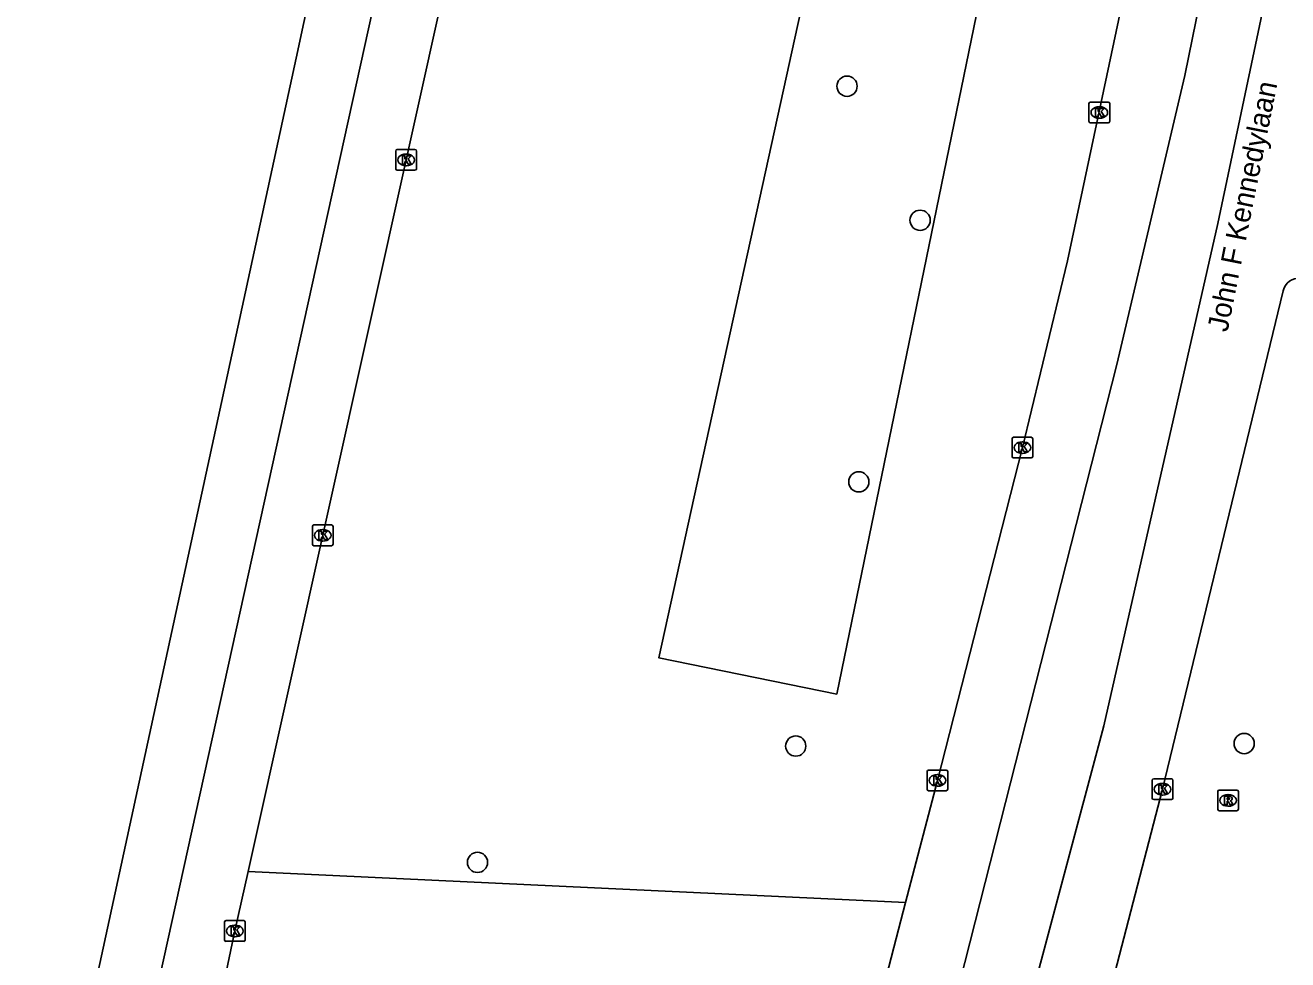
# Model space of a CAD drawing. Extents: x 161761 to 162722, y 384793 to 385405.
# Drawn here: x 161766 to 161827, y 384916.7 to 384961.8 of the extents above; entities that cross this region are included whole.
import ezdxf

# ---------------------------------------------------------------- set-up
doc = ezdxf.new("R2010")
doc.units = 0
for name, color, linetype in [('IMGEO_Berm_groen', 7, 'Continuous'), ('IMGEO_Boom', 7, 'Continuous'), ('IMGEO_Kolk', 7, 'Continuous'), ('IMGEO_Openbare_ruimte_label', 7, 'Continuous'), ('IMGEO_Rijbaan_regionaal_gesloten', 7, 'Continuous'), ('IMGEO_Rioolput', 7, 'Continuous')]:
    doc.layers.add(name, color=color, linetype=linetype)

msp = doc.modelspace()

# ---------------------------------------------------------------- linework, layer by layer
at = {"layer": 'IMGEO_Berm_groen'}
for points in [[(161811.624, 384999.634), (161819.406, 384998.551), (161805.199, 384929.475), (161796.614, 384931.218), (161811.624, 384999.634)], [(161776.768, 384920.915), (161777.782, 384920.867), (161807.508, 384919.459), (161808.527, 384919.411)]]:
    msp.add_lwpolyline(points, dxfattribs=at)
at = {"layer": 'IMGEO_Boom'}
for centre in [(161805.698, 384958.814), (161809.226, 384952.345), (161806.267, 384939.718), (161803.22, 384926.965), (161824.877, 384927.086), (161787.85, 384921.352)]:
    msp.add_circle(centre, 0.489, dxfattribs=at)
at = {"layer": 'IMGEO_Kolk'}
for p, q in [((161817.383, 384957.122), (161817.383, 384957.974)), ((161817.458, 384958.048), (161818.31, 384958.048)), ((161817.871, 384957.828), (161817.896, 384957.828)), ((161818.384, 384957.974), (161818.384, 384957.122)), ((161817.894, 384957.268), (161817.869, 384957.268)), ((161818.31, 384957.048), (161817.458, 384957.048)), ((161783.903, 384954.833), (161783.903, 384955.685)), ((161783.978, 384955.759), (161784.83, 384955.759)), ((161784.391, 384955.539), (161784.416, 384955.539)), ((161784.904, 384955.685), (161784.904, 384954.833)), ((161784.83, 384954.759), (161783.978, 384954.759)), ((161784.414, 384954.979), (161784.389, 384954.979)), ((161813.667, 384940.945), (161813.667, 384941.797)), ((161813.742, 384941.871), (161814.594, 384941.871)), ((161814.155, 384941.651), (161814.18, 384941.651)), ((161814.668, 384941.797), (161814.668, 384940.945)), ((161814.594, 384940.871), (161813.742, 384940.871)), ((161814.178, 384941.091), (161814.153, 384941.091)), ((161779.949, 384937.636), (161780.801, 384937.636)), ((161779.874, 384936.71), (161779.874, 384937.562)), ((161780.362, 384937.416), (161780.387, 384937.416)), ((161780.875, 384937.562), (161780.875, 384936.71)), ((161780.801, 384936.636), (161779.949, 384936.636)), ((161780.385, 384936.856), (161780.36, 384936.856)), ((161809.562, 384924.881), (161809.562, 384925.733)), ((161809.637, 384925.807), (161810.489, 384925.807)), ((161810.05, 384925.587), (161810.075, 384925.587)), ((161810.563, 384925.733), (161810.563, 384924.881)), ((161810.073, 384925.027), (161810.048, 384925.027)), ((161820.435, 384924.455), (161820.435, 384925.307)), ((161820.51, 384925.381), (161821.362, 384925.381)), ((161820.923, 384925.161), (161820.948, 384925.161)), ((161821.436, 384925.307), (161821.436, 384924.455)), ((161810.489, 384924.807), (161809.637, 384924.807)), ((161821.362, 384924.381), (161820.51, 384924.381)), ((161820.946, 384924.601), (161820.921, 384924.601)), ((161775.63, 384917.613), (161775.63, 384918.465)), ((161775.705, 384918.539), (161776.557, 384918.539)), ((161776.118, 384918.319), (161776.143, 384918.319)), ((161776.631, 384918.465), (161776.631, 384917.613)), ((161776.557, 384917.539), (161775.705, 384917.539)), ((161776.141, 384917.759), (161776.116, 384917.759))]:
    msp.add_line(p, q, dxfattribs=at)
for points in [[(161817.383, 384957.122), (161817.383, 384957.974)], [(161817.458, 384958.048), (161818.31, 384958.048)], [(161817.704, 384957.748), (161817.827, 384957.748), (161817.827, 384957.597), (161817.957, 384957.748), (161818.121, 384957.748), (161817.975, 384957.597), (161818.128, 384957.348), (161817.976, 384957.348), (161817.891, 384957.512), (161817.827, 384957.445), (161817.827, 384957.348), (161817.704, 384957.348), (161817.704, 384957.748)], [(161818.384, 384957.974), (161818.384, 384957.122)], [(161818.31, 384957.048), (161817.458, 384957.048)], [(161783.903, 384954.833), (161783.903, 384955.685)], [(161783.978, 384955.759), (161784.83, 384955.759)], [(161784.224, 384955.459), (161784.347, 384955.459), (161784.347, 384955.308), (161784.477, 384955.459), (161784.641, 384955.459), (161784.495, 384955.308), (161784.648, 384955.059), (161784.496, 384955.059), (161784.411, 384955.223), (161784.347, 384955.156), (161784.347, 384955.059), (161784.224, 384955.059), (161784.224, 384955.459)], [(161784.904, 384955.685), (161784.904, 384954.833)], [(161784.83, 384954.759), (161783.978, 384954.759)], [(161813.667, 384940.945), (161813.667, 384941.797)], [(161813.742, 384941.871), (161814.594, 384941.871)], [(161813.988, 384941.571), (161814.111, 384941.571), (161814.111, 384941.42), (161814.241, 384941.571), (161814.405, 384941.571), (161814.259, 384941.42), (161814.412, 384941.171), (161814.26, 384941.171), (161814.175, 384941.335), (161814.111, 384941.268), (161814.111, 384941.171), (161813.988, 384941.171), (161813.988, 384941.571)], [(161814.668, 384941.797), (161814.668, 384940.945)], [(161814.594, 384940.871), (161813.742, 384940.871)], [(161779.949, 384937.636), (161780.801, 384937.636)], [(161779.874, 384936.71), (161779.874, 384937.562)], [(161780.195, 384937.336), (161780.318, 384937.336), (161780.318, 384937.185), (161780.448, 384937.336), (161780.612, 384937.336), (161780.466, 384937.185), (161780.619, 384936.936), (161780.467, 384936.936), (161780.382, 384937.1), (161780.318, 384937.033), (161780.318, 384936.936), (161780.195, 384936.936), (161780.195, 384937.336)], [(161780.875, 384937.562), (161780.875, 384936.71)], [(161780.801, 384936.636), (161779.949, 384936.636)], [(161809.562, 384924.881), (161809.562, 384925.733)], [(161809.637, 384925.807), (161810.489, 384925.807)], [(161809.883, 384925.507), (161810.006, 384925.507), (161810.006, 384925.356), (161810.136, 384925.507), (161810.3, 384925.507), (161810.154, 384925.356), (161810.307, 384925.107), (161810.155, 384925.107), (161810.07, 384925.271), (161810.006, 384925.204), (161810.006, 384925.107), (161809.883, 384925.107), (161809.883, 384925.507)], [(161810.563, 384925.733), (161810.563, 384924.881)], [(161820.435, 384924.455), (161820.435, 384925.307)], [(161820.51, 384925.381), (161821.362, 384925.381)], [(161820.756, 384925.081), (161820.879, 384925.081), (161820.879, 384924.93), (161821.009, 384925.081), (161821.173, 384925.081), (161821.027, 384924.93), (161821.18, 384924.681), (161821.028, 384924.681), (161820.943, 384924.845), (161820.879, 384924.778), (161820.879, 384924.681), (161820.756, 384924.681), (161820.756, 384925.081)], [(161821.436, 384925.307), (161821.436, 384924.455)], [(161810.489, 384924.807), (161809.637, 384924.807)], [(161821.362, 384924.381), (161820.51, 384924.381)], [(161775.63, 384917.613), (161775.63, 384918.465)], [(161775.705, 384918.539), (161776.557, 384918.539)], [(161775.951, 384918.239), (161776.074, 384918.239), (161776.074, 384918.088), (161776.204, 384918.239), (161776.368, 384918.239), (161776.222, 384918.088), (161776.375, 384917.839), (161776.223, 384917.839), (161776.138, 384918.003), (161776.074, 384917.936), (161776.074, 384917.839), (161775.951, 384917.839), (161775.951, 384918.239)], [(161776.631, 384918.465), (161776.631, 384917.613)], [(161776.557, 384917.539), (161775.705, 384917.539)]]:
    msp.add_lwpolyline(points, dxfattribs=at)
for centre, start, end in [((161817.46, 384957.972), 91.55205, 178.44795), ((161817.46, 384957.972), 91.55205, 178.44795), ((161818.308, 384957.972), 1.55205, 88.44795), ((161818.308, 384957.972), 1.55205, 88.44795), ((161817.46, 384957.124), 181.55205, 268.44795), ((161817.46, 384957.124), 181.55205, 268.44795), ((161818.308, 384957.124), 271.55205, 358.44795), ((161818.308, 384957.124), 271.55205, 358.44795), ((161783.98, 384955.683), 91.55205, 178.44795), ((161783.98, 384955.683), 91.55205, 178.44795), ((161784.828, 384955.683), 1.55205, 88.44795), ((161784.828, 384955.683), 1.55205, 88.44795), ((161783.98, 384954.835), 181.55205, 268.44795), ((161783.98, 384954.835), 181.55205, 268.44795), ((161784.828, 384954.835), 271.55205, 358.44795), ((161784.828, 384954.835), 271.55205, 358.44795), ((161813.744, 384941.795), 91.55205, 178.44795), ((161813.744, 384941.795), 91.55205, 178.44795), ((161814.592, 384941.795), 1.55205, 88.44795), ((161814.592, 384941.795), 1.55205, 88.44795), ((161813.744, 384940.947), 181.55205, 268.44795), ((161813.744, 384940.947), 181.55205, 268.44795), ((161814.592, 384940.947), 271.55205, 358.44795), ((161814.592, 384940.947), 271.55205, 358.44795), ((161779.951, 384937.56), 91.55205, 178.44795), ((161779.951, 384937.56), 91.55205, 178.44795), ((161780.799, 384937.56), 1.55205, 88.44795), ((161780.799, 384937.56), 1.55205, 88.44795), ((161779.951, 384936.712), 181.55205, 268.44795), ((161779.951, 384936.712), 181.55205, 268.44795), ((161780.799, 384936.712), 271.55205, 358.44795), ((161780.799, 384936.712), 271.55205, 358.44795), ((161809.639, 384925.731), 91.55205, 178.44795), ((161809.639, 384925.731), 91.55205, 178.44795), ((161810.487, 384925.731), 1.55205, 88.44795), ((161810.487, 384925.731), 1.55205, 88.44795), ((161809.639, 384924.883), 181.55205, 268.44795), ((161809.639, 384924.883), 181.55205, 268.44795), ((161810.487, 384924.883), 271.55205, 358.44795), ((161810.487, 384924.883), 271.55205, 358.44795), ((161820.512, 384925.305), 91.55205, 178.44795), ((161820.512, 384925.305), 91.55205, 178.44795), ((161821.36, 384925.305), 1.55205, 88.44795), ((161821.36, 384925.305), 1.55205, 88.44795), ((161820.512, 384924.457), 181.55205, 268.44795), ((161820.512, 384924.457), 181.55205, 268.44795), ((161821.36, 384924.457), 271.55205, 358.44795), ((161821.36, 384924.457), 271.55205, 358.44795), ((161775.707, 384918.463), 91.55205, 178.44795), ((161775.707, 384918.463), 91.55205, 178.44795), ((161776.555, 384918.463), 1.55205, 88.44795), ((161776.555, 384918.463), 1.55205, 88.44795), ((161775.707, 384917.615), 181.55205, 268.44795), ((161775.707, 384917.615), 181.55205, 268.44795), ((161776.555, 384917.615), 271.55205, 358.44795), ((161776.555, 384917.615), 271.55205, 358.44795)]:
    msp.add_arc(centre, 0.0765, start, end, dxfattribs=at)
for centre, major_axis, ratio, start_param, end_param in [((161817.87, 384957.548), (-0.387, 0.002), 0.722429, 4.712389, 7.853982), ((161817.895, 384957.548), (-0.39, 0.002), 0.717154, 1.570796, 4.712389), ((161784.39, 384955.259), (-0.387, 0.002), 0.722429, 4.712389, 7.853982), ((161784.415, 384955.259), (-0.39, 0.002), 0.717154, 1.570796, 4.712389), ((161814.154, 384941.371), (-0.387, 0.002), 0.722429, 4.712389, 7.853982), ((161814.179, 384941.371), (-0.39, 0.002), 0.717154, 1.570796, 4.712389), ((161780.361, 384937.136), (-0.387, 0.002), 0.722429, 4.712389, 7.853982), ((161780.386, 384937.136), (-0.39, 0.002), 0.717154, 1.570796, 4.712389), ((161810.049, 384925.307), (-0.387, 0.002), 0.722429, 4.712389, 7.853982), ((161810.074, 384925.307), (-0.39, 0.002), 0.717154, 1.570796, 4.712389), ((161820.922, 384924.881), (-0.387, 0.002), 0.722429, 4.712389, 7.853982), ((161820.947, 384924.881), (-0.39, 0.002), 0.717154, 1.570796, 4.712389), ((161776.117, 384918.039), (-0.387, 0.002), 0.722429, 4.712389, 7.853982), ((161776.142, 384918.039), (-0.39, 0.002), 0.717154, 1.570796, 4.712389)]:
    msp.add_ellipse(centre, major_axis=major_axis, ratio=ratio, start_param=start_param, end_param=end_param, dxfattribs=at)
at = {"layer": 'IMGEO_Rijbaan_regionaal_gesloten'}
for points in [[(161833.852, 385205.796), (161833.88, 385197.119), (161833.885, 385195.677), (161833.919, 385184.644), (161833.69, 385183.423), (161832.206, 385175.263), (161830.174, 385165.209), (161826.384, 385147.025), (161822.909, 385130.834), (161819.236, 385113.65), (161815.529, 385096.473), (161811.225, 385076.335), (161806.891, 385056.221), (161802.572, 385036.101), (161798.026, 385016.018), (161793.64, 384996.834), (161793.414, 384995.395), (161788.738, 384974.604), (161788.434, 384973.388), (161776.768, 384920.915)], [(161766.008, 384899.854), (161779.088, 384960.168), (161797.461, 385045.58), (161797.509, 385045.802), (161814.834, 385126.603), (161816.242, 385133.166)], [(161819.816, 385132.405), (161819.233, 385129.707), (161818.648, 385127.01), (161818.06, 385124.314), (161817.47, 385121.618), (161816.869, 385118.927), (161816.281, 385116.228), (161797.041, 385026.639), (161795.131, 385019.479), (161785.292, 384973.871), (161770.97, 384908.832), (161770.104, 384900.192), (161770.02, 384896.252), (161769.959, 384893.387), (161770.564, 384886.735)], [(161847.678, 385126.475), (161845.742, 385106.666), (161842.993, 385081.473), (161839.52, 385055.945), (161835.903, 385032.779), (161831.569, 385007.397), (161829.399, 384995.814), (161825.492, 384976.413), (161822.019, 384959.327), (161818.724, 384945.388), (161808.45, 384904.992), (161805.49, 384894.455), (161802.858, 384885.087)], [(161806.301, 384884.91), (161808.959, 384894.325), (161812.031, 384905.208), (161818.108, 384927.94), (161823.605, 384952.19), (161832.136, 384992.657), (161842.706, 385055.699), (161851.137, 385125.739)], [(161808.527, 384919.411), (161810.063, 384925.307), (161814.168, 384941.371), (161816.347, 384950.387), (161822.556, 384979.674)], [(161812.619, 384893.993), (161812.623, 384894.009), (161816.113, 384906.346), (161820.936, 384924.881), (161826.126, 384946.341), (161826.755, 384948.946)], [(161776.768, 384920.915), (161776.129, 384918.039), (161775.05, 384912.914)], [(161801.851, 384894.591), (161802.106, 384895.489), (161803.561, 384900.798), (161805.893, 384909.296), (161808.527, 384919.411)]]:
    msp.add_lwpolyline(points, dxfattribs=at)
msp.add_arc((161827.538, 384948.747), 0.808, 6.91288, 165.72293, dxfattribs=at)
at = {"layer": 'IMGEO_Rioolput'}
for p, q in [((161823.674, 384924.841), (161824.526, 384924.841)), ((161823.599, 384923.915), (161823.599, 384924.767)), ((161824.087, 384924.621), (161824.112, 384924.621)), ((161824.6, 384924.767), (161824.6, 384923.915)), ((161824.526, 384923.841), (161823.674, 384923.841)), ((161824.11, 384924.061), (161824.085, 384924.061))]:
    msp.add_line(p, q, dxfattribs=at)
for points in [[(161823.674, 384924.841), (161824.526, 384924.841)], [(161823.599, 384923.915), (161823.599, 384924.767)], [(161824.188, 384924.539), (161823.936, 384924.541), (161823.936, 384924.141)], [(161823.936, 384924.141), (161824.06, 384924.141), (161824.06, 384924.303), (161824.071, 384924.303)], [(161824.114, 384924.46), (161824.06, 384924.46), (161824.06, 384924.379)], [(161824.06, 384924.379), (161824.112, 384924.379)], [(161824.118, 384924.274), (161824.189, 384924.141), (161824.329, 384924.141), (161824.264, 384924.267)], [(161824.6, 384924.767), (161824.6, 384923.915)], [(161824.526, 384923.841), (161823.674, 384923.841)]]:
    msp.add_lwpolyline(points, dxfattribs=at)
for centre, radius, start, end in [((161823.676, 384924.765), 0.0765, 91.55205, 178.44795), ((161823.676, 384924.765), 0.0765, 91.55205, 178.44795), ((161824.524, 384924.765), 0.0765, 1.55205, 88.44795), ((161824.524, 384924.765), 0.0765, 1.55205, 88.44795), ((161824.07, 384924.25), 0.0533, 26.02933, 88.69889), ((161824.096, 384924.568), 0.19, 274.7715, 282.96867), ((161824.12, 384924.364), 0.0964, 77.00612, 93.18647), ((161824.134, 384924.421), 0.0378, 276.66336, 79.67722), ((161824.187, 384924.429), 0.109, 350.36119, 89.41601), ((161824.185, 384924.429), 0.112, 277.58423, 350.98172), ((161824.169, 384924.214), 0.108, 29.51342, 73.79051), ((161823.676, 384923.917), 0.0765, 181.55205, 268.44795), ((161823.676, 384923.917), 0.0765, 181.55205, 268.44795), ((161824.524, 384923.917), 0.0765, 271.55205, 358.44795), ((161824.524, 384923.917), 0.0765, 271.55205, 358.44795)]:
    msp.add_arc(centre, radius, start, end, dxfattribs=at)
for centre, major_axis, ratio, start_param, end_param in [((161824.086, 384924.341), (-0.387, 0.002), 0.722429, 4.712389, 7.853982), ((161824.111, 384924.341), (-0.39, 0.002), 0.717154, 1.570796, 4.712389)]:
    msp.add_ellipse(centre, major_axis=major_axis, ratio=ratio, start_param=start_param, end_param=end_param, dxfattribs=at)

# ---------------------------------------------------------------- texts
at = {"layer": 'IMGEO_Openbare_ruimte_label'}
msp.add_text('John F Kennedylaan', height=1, rotation=78.63386, dxfattribs=at).set_placement((161824.07, 384946.914))

doc.saveas('drawing.dxf')
